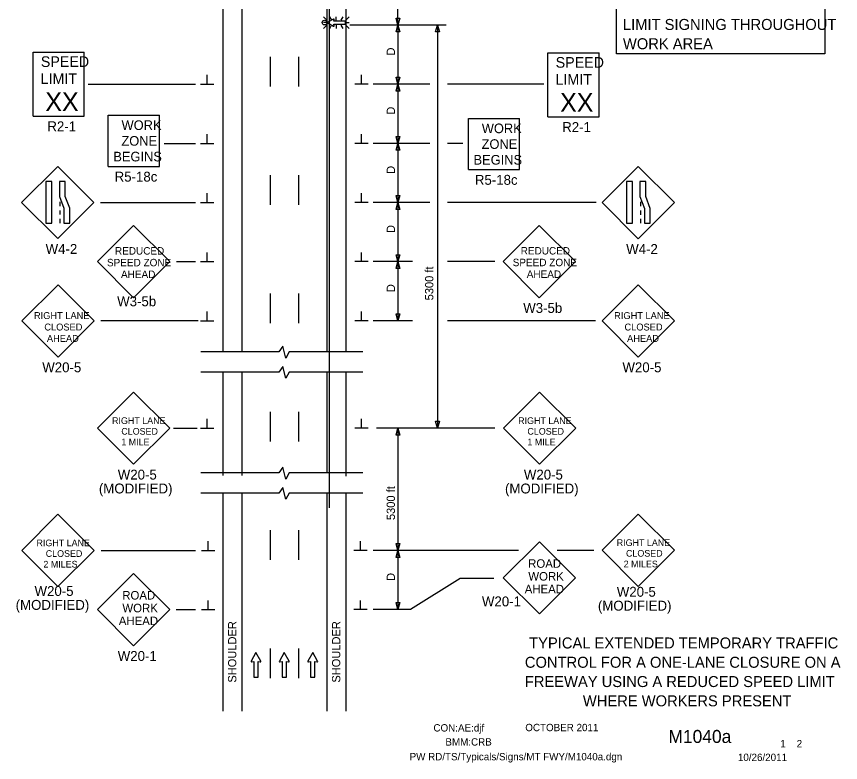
# Model space of a CAD drawing. Extents: x 16733 to 18475, y 5932 to 6964.
# Drawn here: x 16738 to 17435, y 5932 to 6562 of the extents above; entities that cross this region are included whole.
import ezdxf

# ---------------------------------------------------------------- set-up
doc = ezdxf.new("R2010")
doc.units = 0
for name, color, linetype in [('ALI_LEGAL_EX', 7, 'Continuous'), ('BORDER', 7, 'Continuous'), ('BORDER_SIGNAL_WO', 7, 'Continuous'), ('MT_SCRATCH_LEVEL_E', 7, 'Continuous'), ('PAVT_EDGE_EX', 7, 'Continuous'), ('TRAFFIC_SIGNS_PR', 7, 'Continuous'), ('TYPICAL_TEXT_DIMEN_EX', 7, 'Continuous'), ('TYPICAL_TEXT_DIMEN_PR', 7, 'Continuous')]:
    doc.layers.add(name, color=color, linetype=linetype)

msp = doc.modelspace()

# ---------------------------------------------------------------- linework, layer by layer
at = {"layer": 'ALI_LEGAL_EX'}
msp.add_line((17002.72, 6964.07), (17002.72, 6147.1), dxfattribs=at)
for points in [[(16952.72, 6528.28), (16952.72, 6503.28)], [(16976.72, 6528.28), (16976.72, 6503.28)], [(16952.72, 6428.28), (16952.72, 6403.28)], [(16976.72, 6428.28), (16976.72, 6403.28)], [(16952.72, 6328.28), (16952.72, 6303.28)], [(16976.72, 6328.28), (16976.72, 6303.28)], [(16952.72, 6228.28), (16952.72, 6203.28)], [(16976.72, 6228.28), (16976.72, 6203.28)], [(16952.72, 6128.28), (16952.72, 6103.28)], [(16976.72, 6128.28), (16976.72, 6103.28)], [(16952.72, 6028.28), (16952.72, 6003.28)], [(16976.72, 6028.28), (16976.72, 6003.28)]]:
    msp.add_lwpolyline(points, dxfattribs=at)
at = {"layer": 'MT_SCRATCH_LEVEL_E'}
for p, q in [((16940.72, 6024.82), (16936.61, 6017.57)), ((16944.87, 6017.57), (16940.72, 6024.82)), ((16964.62, 6024.82), (16960.51, 6017.57)), ((16968.77, 6017.57), (16964.62, 6024.82)), ((16988.68, 6024.82), (16984.56, 6017.57)), ((16992.82, 6017.57), (16988.68, 6024.82)), ((16937.09, 6016.89), (16938.87, 6017.21)), ((16938.87, 6017.21), (16938.87, 6003.95)), ((16942.61, 6003.95), (16942.61, 6017.21)), ((16942.61, 6017.21), (16944.39, 6016.89)), ((16960.99, 6016.89), (16962.77, 6017.21)), ((16962.77, 6017.21), (16962.77, 6003.95)), ((16966.51, 6003.95), (16966.51, 6017.21)), ((16966.51, 6017.21), (16968.29, 6016.89)), ((16985.05, 6016.89), (16986.82, 6017.21)), ((16986.82, 6017.21), (16986.82, 6003.95)), ((16990.57, 6003.95), (16990.57, 6017.21)), ((16990.57, 6017.21), (16992.34, 6016.89)), ((16938.87, 6003.95), (16942.61, 6003.95)), ((16962.77, 6003.95), (16966.51, 6003.95)), ((16986.82, 6003.95), (16990.57, 6003.95))]:
    msp.add_line(p, q, dxfattribs=at)
for centre, start, end in [((16937.02, 6017.35), 150.42484, 279.96381), ((16944.46, 6017.35), 260.03619, 29.77312), ((16960.92, 6017.35), 150.42484, 279.96381), ((16968.36, 6017.35), 260.03619, 29.77312), ((16984.97, 6017.35), 150.42484, 279.96381), ((16992.41, 6017.35), 260.03619, 29.77312)]:
    msp.add_arc(centre, 0.463, start, end, dxfattribs=at)
at = {"layer": 'PAVT_EDGE_EX'}
for p, q in [((16912.72, 6926.76), (16912.72, 6278.89)), ((16928.72, 6926.76), (16928.72, 6278.89)), ((17016.72, 6926.76), (17016.72, 6278.89)), ((17000.72, 6689.4), (17000.72, 6278.89)), ((16912.72, 6261.75), (16912.72, 6176.61)), ((16928.72, 6261.75), (16928.72, 6176.61)), ((17000.72, 6261.75), (17000.72, 6176.61)), ((17016.72, 6261.75), (17016.72, 6176.61)), ((16912.72, 6224.8), (16912.72, 6174.41)), ((16928.72, 6224.8), (16928.72, 6174.41)), ((17000.72, 6224.8), (17000.72, 6177.32)), ((17016.72, 6224.8), (17016.72, 6173.99)), ((16912.72, 6159.47), (16912.72, 5975.18)), ((16928.72, 6159.47), (16928.72, 5975.18)), ((17000.72, 6159.47), (17000.72, 5975.18)), ((17016.72, 6159.47), (17016.72, 5975.18))]:
    msp.add_line(p, q, dxfattribs=at)
at = {"layer": 'TRAFFIC_SIGNS_PR'}
for p, q in [((16997.71, 6562.09), (17000.53, 6559.27)), ((17004.43, 6559.91), (17003.17, 6562.09)), ((17008.61, 6559.27), (17008.61, 6562.09)), ((17012.75, 6559.27), (17014.38, 6562.09)), ((17016.7, 6559.27), (17019.52, 6562.09)), ((17000.53, 6557.24), (16997.71, 6557.24)), ((16997.71, 6552.39), (17000.53, 6555.21)), ((17003.15, 6552.39), (17004.35, 6554.48)), ((17008.61, 6555.21), (17008.61, 6552.39)), ((17014.4, 6552.39), (17012.77, 6555.21)), ((17016.7, 6557.24), (17019.52, 6557.24)), ((17016.7, 6555.21), (17019.52, 6552.39)), ((16752.49, 6532.31), (16795.69, 6532.31)), ((16752.49, 6478.31), (16752.49, 6532.31)), ((16795.69, 6478.31), (16795.69, 6532.31)), ((17187.47, 6531.69), (17230.67, 6531.69)), ((17187.47, 6477.69), (17187.47, 6531.69)), ((17230.67, 6477.69), (17230.67, 6531.69)), ((16752.49, 6478.31), (16795.69, 6478.31)), ((16815.92, 6435.74), (16815.92, 6478.94)), ((16815.92, 6478.94), (16859.12, 6478.94)), ((16859.12, 6435.74), (16859.12, 6478.94)), ((17120.27, 6433.04), (17120.27, 6476.24)), ((17120.27, 6476.24), (17163.47, 6476.24)), ((17163.47, 6433.04), (17163.47, 6476.24)), ((17187.47, 6477.69), (17230.67, 6477.69)), ((16773.21, 6435.75), (16742.66, 6405.21)), ((16803.75, 6405.21), (16773.21, 6435.75)), ((16815.92, 6435.74), (16859.12, 6435.74)), ((17263.71, 6435.68), (17233.17, 6405.13)), ((17294.26, 6405.13), (17263.71, 6435.68)), ((17120.27, 6433.04), (17163.47, 6433.04)), ((16775.05, 6405.76), (16775.05, 6402.16)), ((17265.56, 6405.68), (17265.56, 6402.08)), ((16742.66, 6405.21), (16773.21, 6374.66)), ((16773.21, 6374.66), (16803.75, 6405.21)), ((16775.05, 6398.56), (16775.05, 6394.96)), ((17233.17, 6405.13), (17263.71, 6374.58)), ((17263.71, 6374.58), (17294.26, 6405.13)), ((17265.56, 6398.48), (17265.56, 6394.88)), ((16775.05, 6391.36), (16775.05, 6387.76)), ((16837.28, 6385.76), (16806.74, 6355.21)), ((16867.83, 6355.21), (16837.28, 6385.76)), ((17180.09, 6385.85), (17149.54, 6355.31)), ((17210.64, 6355.31), (17180.09, 6385.85)), ((17265.56, 6391.28), (17265.56, 6387.68)), ((16806.74, 6355.21), (16837.28, 6324.67)), ((16837.28, 6324.67), (16867.83, 6355.21)), ((17149.54, 6355.31), (17180.09, 6324.76)), ((17180.09, 6324.76), (17210.64, 6355.31)), ((16773.49, 6335.68), (16742.94, 6305.14)), ((16804.03, 6305.14), (16773.49, 6335.68)), ((17263.67, 6335.68), (17233.12, 6305.14)), ((17294.22, 6305.14), (17263.67, 6335.68)), ((16742.94, 6305.14), (16773.49, 6274.59)), ((16773.49, 6274.59), (16804.03, 6305.14)), ((17233.12, 6305.14), (17263.67, 6274.59)), ((17263.67, 6274.59), (17294.22, 6305.14)), ((16837.29, 6244.99), (16806.74, 6214.44)), ((16867.83, 6214.44), (16837.29, 6244.99)), ((17180.39, 6244.99), (17149.84, 6214.44)), ((17210.93, 6214.44), (17180.39, 6244.99)), ((16806.74, 6214.44), (16837.29, 6183.9)), ((16837.29, 6183.9), (16867.83, 6214.44)), ((17149.84, 6214.44), (17180.39, 6183.9)), ((17180.39, 6183.9), (17210.93, 6214.44)), ((16773.43, 6141.68), (16742.88, 6111.13)), ((16803.97, 6111.13), (16773.43, 6141.68)), ((17263.69, 6141.87), (17233.14, 6111.32)), ((17294.23, 6111.32), (17263.69, 6141.87)), ((17180.23, 6118.52), (17149.68, 6087.97)), ((17210.78, 6087.97), (17180.23, 6118.52)), ((16742.88, 6111.13), (16773.43, 6080.58)), ((16773.43, 6080.58), (16803.97, 6111.13)), ((17233.14, 6111.32), (17263.69, 6080.77)), ((17263.69, 6080.77), (17294.23, 6111.32)), ((16837.27, 6091.68), (16806.72, 6061.13)), ((16867.82, 6061.13), (16837.27, 6091.68)), ((17149.68, 6087.97), (17180.23, 6057.43)), ((17180.23, 6057.43), (17210.78, 6087.97)), ((16806.72, 6061.13), (16837.27, 6030.58)), ((16837.27, 6030.58), (16867.82, 6061.13))]:
    msp.add_line(p, q, dxfattribs=at)
for points in [[(17006.29, 6560.26), (17000.98, 6557.24), (17006.29, 6554.2)], [(17006.79, 6554.56), (17006.56, 6555.86), (17016.28, 6555.86), (17016.28, 6558.6), (17006.56, 6558.6), (17006.79, 6559.9)]]:
    msp.add_lwpolyline(points, dxfattribs=at)
for points in [[(16763.2, 6422.91), (16763.2, 6387.76), (16768.25, 6387.76), (16768.25, 6422.91)], [(16774.6, 6422.91), (16774.6, 6410.33), (16778.36, 6400.34), (16778.36, 6387.76), (16783.42, 6387.76), (16783.42, 6400.34), (16779.66, 6410.33), (16779.66, 6422.91)], [(17253.71, 6422.84), (17253.71, 6387.68), (17258.76, 6387.68), (17258.76, 6422.84)], [(17265.11, 6422.84), (17265.11, 6410.26), (17268.87, 6400.26), (17268.87, 6387.68), (17273.93, 6387.68), (17273.93, 6400.26), (17270.16, 6410.26), (17270.16, 6422.84)]]:
    msp.add_lwpolyline(points, close=True, dxfattribs=at)
msp.add_circle((16998.7, 6557.32), 2, dxfattribs=at)
for centre, start, end in [((17006.45, 6559.96), 350.73078, 118.89165), ((17006.45, 6554.5), 241.48329, 9.95933)]:
    msp.add_arc(centre, 0.341, start, end, dxfattribs=at)
at = {"layer": 'TYPICAL_TEXT_DIMEN_EX'}
msp.add_lwpolyline([(17245.38, 6596.3), (17421.3, 6596.3), (17421.3, 6530.87), (17245.38, 6530.87)], close=True, dxfattribs=at)
at = {"layer": 'TYPICAL_TEXT_DIMEN_PR'}
for p, q in [((17060.72, 6555.21), (17060.72, 6589.4)), ((17060.72, 6555.21), (17059.15, 6561.07)), ((17059.15, 6561.07), (17060.72, 6561.07)), ((17060.72, 6561.07), (17062.29, 6561.07)), ((17062.29, 6561.07), (17060.72, 6555.21)), ((17101.49, 6555.21), (17020.02, 6555.21)), ((17059.15, 6549.35), (17060.72, 6555.21)), ((17060.72, 6555.21), (17060.72, 6505.21)), ((17060.72, 6555.21), (17062.29, 6549.35)), ((17092.53, 6549.35), (17094.11, 6555.21)), ((17094.11, 6555.21), (17095.68, 6549.35)), ((17094.11, 6555.21), (17094.11, 6214.44)), ((17060.72, 6549.35), (17059.15, 6549.35)), ((17062.29, 6549.35), (17060.72, 6549.35)), ((17094.11, 6549.35), (17092.53, 6549.35)), ((17095.68, 6549.35), (17094.11, 6549.35)), ((16899.6, 6505.21), (16899.6, 6512.99)), ((17029.85, 6505.21), (17029.85, 6512.99)), ((17060.72, 6505.21), (17059.15, 6511.07)), ((17059.15, 6511.07), (17060.72, 6511.07)), ((17060.72, 6511.07), (17062.29, 6511.07)), ((17062.29, 6511.07), (17060.72, 6505.21)), ((16799.08, 6505.21), (16889.72, 6505.21)), ((16893.97, 6505.21), (16905.22, 6505.21)), ((17035.47, 6505.21), (17024.22, 6505.21)), ((17087.61, 6505.21), (17039.72, 6505.21)), ((17059.15, 6499.35), (17060.72, 6505.21)), ((17060.72, 6505.21), (17060.72, 6455.21)), ((17060.72, 6505.21), (17062.29, 6499.35)), ((17183.89, 6505.21), (17102.67, 6505.21)), ((17060.72, 6499.35), (17059.15, 6499.35)), ((17062.29, 6499.35), (17060.72, 6499.35)), ((16899.6, 6455.21), (16899.6, 6462.99)), ((17029.85, 6455.21), (17029.85, 6462.99)), ((17060.72, 6455.21), (17059.15, 6461.07)), ((17059.15, 6461.07), (17060.72, 6461.07)), ((17060.72, 6461.07), (17062.29, 6461.07)), ((17062.29, 6461.07), (17060.72, 6455.21)), ((16863.25, 6455.21), (16889.72, 6455.21)), ((16893.97, 6455.21), (16905.22, 6455.21)), ((17035.47, 6455.21), (17024.22, 6455.21)), ((17087.61, 6455.21), (17039.72, 6455.21)), ((17059.15, 6449.35), (17060.72, 6455.21)), ((17060.72, 6455.21), (17060.72, 6405.21)), ((17060.72, 6455.21), (17062.29, 6449.35)), ((17115.42, 6455.21), (17102.67, 6455.21)), ((17060.72, 6449.35), (17059.15, 6449.35)), ((17062.29, 6449.35), (17060.72, 6449.35)), ((16899.6, 6405.21), (16899.6, 6412.99)), ((17029.85, 6405.21), (17029.85, 6412.99)), ((17060.72, 6405.21), (17059.15, 6411.07)), ((17059.15, 6411.07), (17060.72, 6411.07)), ((17060.72, 6411.07), (17062.29, 6411.07)), ((17062.29, 6411.07), (17060.72, 6405.21)), ((16809.24, 6405.21), (16889.72, 6405.21)), ((16893.97, 6405.21), (16905.22, 6405.21)), ((17035.47, 6405.21), (17024.22, 6405.21)), ((17087.61, 6405.21), (17039.72, 6405.21)), ((17059.15, 6399.35), (17060.72, 6405.21)), ((17060.72, 6399.35), (17059.15, 6399.35)), ((17060.72, 6405.21), (17060.72, 6355.21)), ((17060.72, 6405.21), (17062.29, 6399.35)), ((17062.29, 6399.35), (17060.72, 6399.35)), ((17228.1, 6405.21), (17102.67, 6405.21)), ((16899.6, 6355.21), (16899.6, 6362.99)), ((17029.85, 6355.21), (17029.85, 6362.99)), ((17060.72, 6355.21), (17059.15, 6361.07)), ((17059.15, 6361.07), (17060.72, 6361.07)), ((17060.72, 6361.07), (17062.29, 6361.07)), ((17062.29, 6361.07), (17060.72, 6355.21)), ((16873.61, 6355.21), (16889.72, 6355.21)), ((16893.97, 6355.21), (16905.22, 6355.21)), ((17035.47, 6355.21), (17024.22, 6355.21)), ((17072.94, 6355.21), (17039.72, 6355.21)), ((17059.15, 6349.35), (17060.72, 6355.21)), ((17060.72, 6355.21), (17060.72, 6305.21)), ((17060.72, 6355.21), (17062.29, 6349.35)), ((17142.58, 6355.21), (17102.67, 6355.21)), ((17060.72, 6349.35), (17059.15, 6349.35)), ((17062.29, 6349.35), (17060.72, 6349.35)), ((16899.6, 6305.21), (16899.6, 6312.99)), ((17029.85, 6305.21), (17029.85, 6312.99)), ((17060.72, 6305.21), (17059.15, 6311.07)), ((17059.15, 6311.07), (17060.72, 6311.07)), ((17060.72, 6311.07), (17062.29, 6311.07)), ((17062.29, 6311.07), (17060.72, 6305.21)), ((16891.81, 6305.21), (16809.7, 6305.21)), ((16893.97, 6305.21), (16905.22, 6305.21)), ((17035.47, 6305.21), (17024.22, 6305.21)), ((17072.94, 6305.21), (17039.72, 6305.21)), ((17102.67, 6305.21), (17102.67, 6305.21)), ((17227.64, 6305.21), (17102.67, 6305.21)), ((16963.32, 6283.69), (16960.07, 6278.89)), ((16966.07, 6273.75), (16963.32, 6283.69)), ((16960.07, 6278.89), (16894.13, 6278.89)), ((16968.81, 6278.89), (16966.07, 6273.75)), ((17031.14, 6278.89), (16968.81, 6278.89)), ((16963.32, 6266.55), (16960.07, 6261.75)), ((16966.07, 6256.61), (16963.32, 6266.55)), ((16960.07, 6261.75), (16894.13, 6261.75)), ((16968.81, 6261.75), (16966.07, 6256.61)), ((17031.14, 6261.75), (16968.81, 6261.75)), ((16899.6, 6214.44), (16899.6, 6222.23)), ((17029.85, 6214.44), (17029.85, 6222.23)), ((17094.11, 6214.44), (17092.53, 6220.3)), ((17092.53, 6220.3), (17094.11, 6220.3)), ((17094.11, 6220.3), (17095.68, 6220.3)), ((17095.68, 6220.3), (17094.11, 6214.44)), ((16871.08, 6214.44), (16891.05, 6214.44)), ((16893.97, 6214.44), (16905.22, 6214.44)), ((17035.47, 6214.44), (17024.22, 6214.44)), ((17142.58, 6214.44), (17042.57, 6214.44)), ((17059.15, 6208.58), (17060.72, 6214.44)), ((17060.72, 6214.44), (17060.72, 6061.13)), ((17060.72, 6214.44), (17062.29, 6208.58)), ((17060.72, 6208.58), (17059.15, 6208.58)), ((17062.29, 6208.58), (17060.72, 6208.58)), ((16960.07, 6176.61), (16894.13, 6176.61)), ((16963.32, 6181.41), (16960.07, 6176.61)), ((16966.07, 6171.47), (16963.32, 6181.41)), ((16968.81, 6176.61), (16966.07, 6171.47)), ((17031.14, 6176.61), (16968.81, 6176.61)), ((16963.32, 6164.27), (16960.07, 6159.47)), ((16966.07, 6154.33), (16963.32, 6164.27)), ((16960.07, 6159.47), (16894.13, 6159.47)), ((16968.81, 6159.47), (16966.07, 6154.33)), ((17031.14, 6159.47), (16968.81, 6159.47)), ((16900.35, 6111.13), (16900.35, 6118.91)), ((17029.1, 6111.13), (17029.1, 6118.91)), ((17060.72, 6111.13), (17059.15, 6116.99)), ((17059.15, 6116.99), (17060.72, 6116.99)), ((17060.72, 6116.99), (17062.29, 6116.99)), ((17062.29, 6116.99), (17060.72, 6111.13)), ((16809.93, 6111.13), (16889.72, 6111.13)), ((16894.72, 6111.13), (16905.97, 6111.13)), ((17034.72, 6111.13), (17023.47, 6111.13)), ((17162.64, 6111.13), (17039.72, 6111.13)), ((17059.15, 6105.27), (17060.72, 6111.13)), ((17060.72, 6111.13), (17060.72, 6061.13)), ((17060.72, 6111.13), (17062.29, 6105.27)), ((17226.26, 6111.13), (17195.13, 6111.13)), ((17060.72, 6105.27), (17059.15, 6105.27)), ((17062.29, 6105.27), (17060.72, 6105.27)), ((17113.34, 6087.41), (17071.41, 6061.13)), ((17141.66, 6087.41), (17113.34, 6087.41)), ((16900.35, 6061.13), (16900.35, 6068.91)), ((17029.1, 6061.13), (17029.1, 6068.91)), ((17060.72, 6061.13), (17059.15, 6066.99)), ((17059.15, 6066.99), (17060.72, 6066.99)), ((17060.72, 6066.99), (17062.29, 6066.99)), ((17062.29, 6066.99), (17060.72, 6061.13)), ((16873.38, 6061.13), (16889.72, 6061.13)), ((16894.72, 6061.13), (16905.97, 6061.13)), ((17034.72, 6061.13), (17023.47, 6061.13)), ((17071.41, 6061.13), (17039.72, 6061.13))]:
    msp.add_line(p, q, dxfattribs=at)

# ---------------------------------------------------------------- texts
at = {"layer": 'BORDER'}
for s, p in [('TYPICAL EXTENDED TEMPORARY TRAFFIC', (17171.54, 6028.24)), ('CONTROL FOR A ONE-LANE CLOSURE ON A', (17167.92, 6011.94)), (' FREEWAY USING A REDUCED SPEED LIMIT', (17164.42, 5995.64)), ('WHERE WORKERS PRESENT', (17216.92, 5979.34))]:
    msp.add_text(s, height=9.3, dxfattribs=at).set_placement(p)
at = {"layer": 'BORDER_SIGNAL_WO'}
for s, height, p in [('CON:AE:djf  ', 6.2, (17090.69, 5958.06)), ('    OCTOBER 2011    ', 6.2, (17159.08, 5958.34)), ('    M1040a   ', 11, (17272.86, 5948.38)), ('BMM:CRB   ', 6.2, (17100.81, 5946.17)), (' 1    2 ', 6.2, (17381.45, 5944.7)), ('PW RD/TS/Typicals/Signs/MT FWY/M1040a.dgn      ', 6.2, (17070.55, 5933.71)), ('10/26/2011    ', 6.2, (17347.93, 5933.13))]:
    msp.add_text(s, height=height, dxfattribs=at).set_placement(p)
at = {"layer": 'TRAFFIC_SIGNS_PR'}
for s, height, p in [('SPEED', 9, (16758.98, 6519.78)), ('SPEED', 9, (17193.96, 6519.16)), ('LIMIT', 9, (16758.8, 6505.38)), ('LIMIT', 9, (17193.78, 6504.76)), ('XX', 15.785, (16762.74, 6482.53)), ('XX', 15.785, (17197.72, 6481.92)), ('R2-1', 8.37, (16764.5, 6465.44)), ('WORK', 8.119, (16827.17, 6466.53)), ('WORK', 8.119, (17131.52, 6463.83)), ('R2-1', 8.37, (17199.48, 6464.82)), ('ZONE', 8.119, (16827.04, 6453.24)), ('ZONE', 8.119, (17131.39, 6450.55)), ('BEGINS', 8.119, (16820.21, 6439.96)), ('BEGINS', 8.119, (17124.56, 6437.26)), ('R5-18c', 8.37, (16821.33, 6422.88)), ('R5-18c', 8.37, (17125.69, 6420.18)), ('W4-2', 8.37, (16763.03, 6361.79)), ('REDUCED', 6.3, (16821.6, 6361.18)), ('REDUCED', 6.3, (17164.41, 6361.28)), ('W4-2', 8.37, (17253.54, 6361.71)), ('SPEED ZONE', 6.3, (16814.84, 6351.28)), ('SPEED ZONE', 6.3, (17157.65, 6351.38)), ('AHEAD', 6.3, (16826.72, 6341.38)), ('AHEAD', 6.3, (17169.53, 6341.48)), ('W3-5b', 8.37, (16823.45, 6317.51)), ('W3-5b', 8.37, (17166.54, 6311.89)), ('RIGHT LANE', 5.85, (16753.15, 6306.71)), ('RIGHT LANE', 5.85, (17243.33, 6306.7)), ('CLOSED', 5.85, (16761.91, 6297.03)), ('CLOSED', 5.85, (17252.1, 6297.03)), ('AHEAD', 5.85, (16764.1, 6287.36)), ('AHEAD', 5.85, (17254.29, 6287.36)), ('W20-5', 8.37, (16760.18, 6261.72)), ('W20-5', 8.37, (17250.37, 6261.72)), ('RIGHT LANE', 5.625, (16819.15, 6217.99)), ('RIGHT LANE', 5.625, (17162.26, 6217.99)), ('CLOSED', 5.625, (16826.98, 6208.99)), ('CLOSED', 5.625, (17170.08, 6208.99)), ('1 MILE', 5.625, (16826.97, 6199.99)), ('1 MILE', 5.625, (17170.08, 6199.99)), ('W20-5', 8.37, (16823.98, 6171.03)), ('W20-5', 8.37, (17167.09, 6171.03)), ('(MODIFIED)', 8.37, (16808.03, 6159.28)), ('(MODIFIED)', 8.37, (17151.14, 6159.28)), ('RIGHT LANE', 5.625, (16755.29, 6114.67)), ('RIGHT LANE', 5.625, (17245.55, 6114.86)), ('CLOSED', 5.625, (16763.12, 6105.67)), ('CLOSED', 5.625, (17253.38, 6105.86)), ('2 MILES', 5.625, (16761.15, 6096.67)), ('ROAD', 7.2, (17170.71, 6096.45)), ('2 MILES', 5.625, (17251.41, 6096.86)), ('WORK', 7.2, (17170.84, 6085.65)), ('W20-5', 8.37, (16753.65, 6072.65)), ('AHEAD', 7.2, (17167.81, 6074.85)), ('W20-5', 8.37, (17245.6, 6071.97)), ('ROAD', 7.2, (16827.76, 6069.61)), ('W20-1', 8.37, (17131.65, 6063.85)), ('(MODIFIED)', 8.37, (16737.7, 6060.9)), ('WORK', 7.2, (16827.88, 6058.81)), ('(MODIFIED)', 8.37, (17229.64, 6060.23)), ('AHEAD', 7.2, (16824.85, 6048.01)), ('W20-1', 8.37, (16823.96, 6017.71))]:
    msp.add_text(s, height=height, dxfattribs=at).set_placement(p)
at = {"layer": 'TYPICAL_TEXT_DIMEN_EX'}
for s, p in [('LIMIT SIGNING THROUGHOUT', (17250.77, 6551.07)), ('WORK AREA', (17250.77, 6534.77))]:
    msp.add_text(s, height=9.3, dxfattribs=at).set_placement(p)
at = {"layer": 'TYPICAL_TEXT_DIMEN_PR'}
for s, p in [('D', (17058.16, 6529.43)), ('D', (17058.16, 6479.43)), ('D', (17058.16, 6429.43)), ('D', (17058.16, 6379.43)), ('5300 ft', (17090.59, 6322.51)), ('D', (17058.16, 6329.43)), ('5300 ft', (17058.16, 6136.77)), ('D', (17058.16, 6085.35)), ('SHOULDER', (16924.14, 5999.36)), ('SHOULDER', (17012, 5999.36))]:
    msp.add_text(s, height=7, rotation=90, dxfattribs=at).set_placement(p)

doc.saveas('drawing.dxf')
